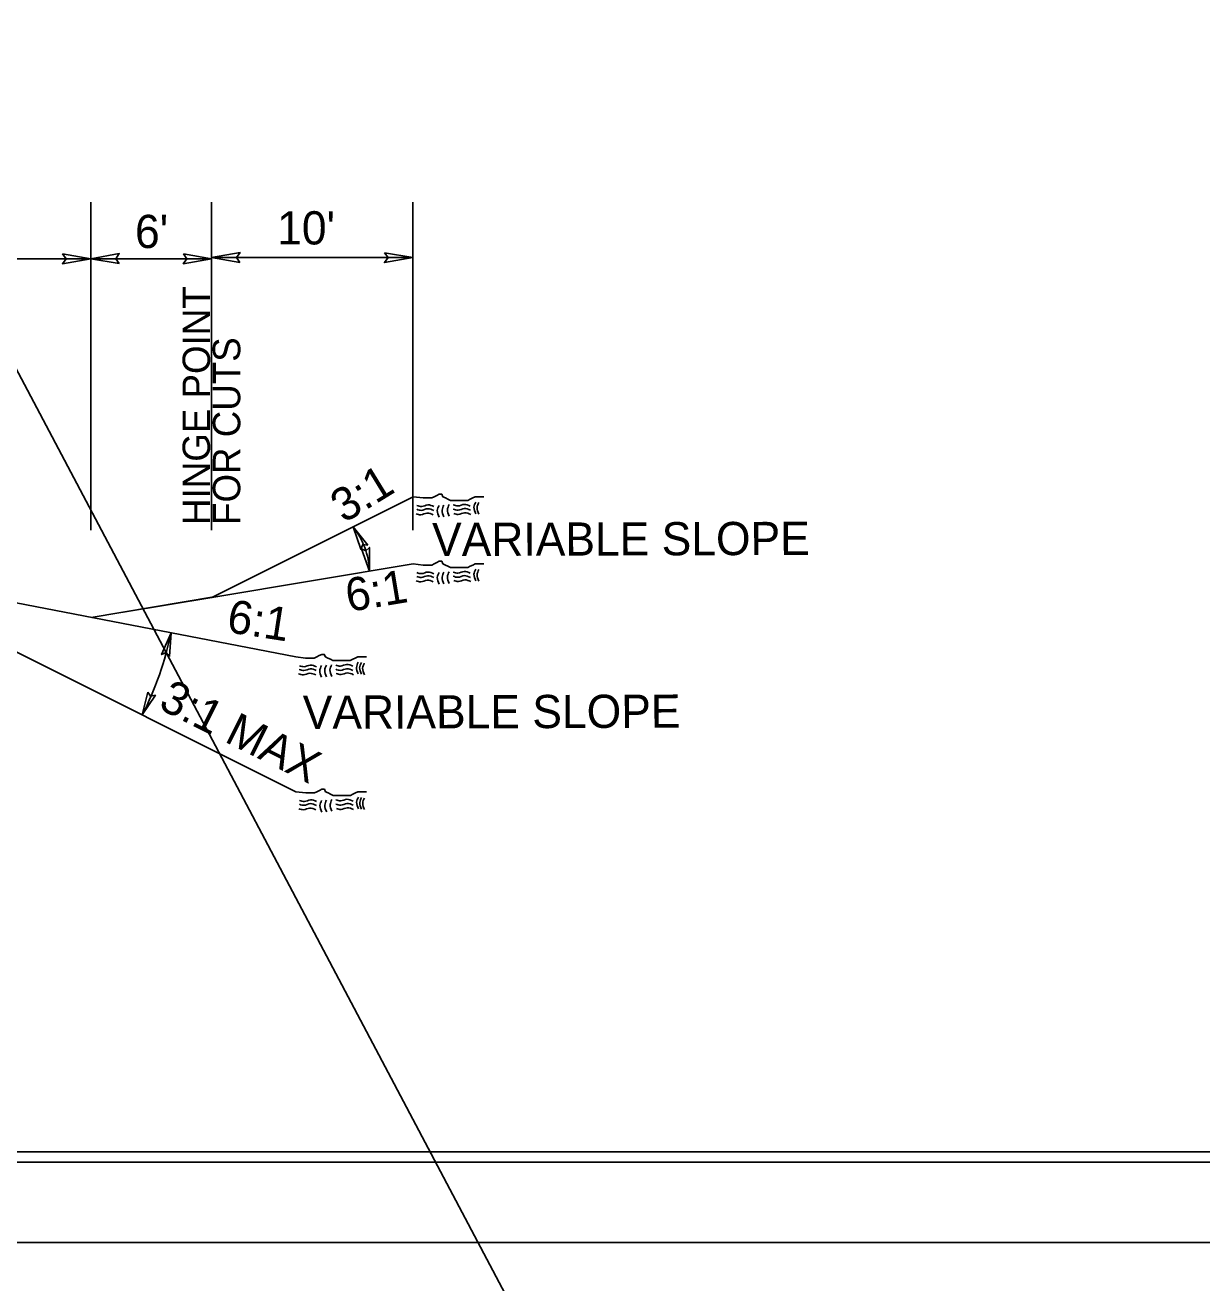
# Model space of a CAD drawing. Extents: x 2241081 to 2251104, y 658534 to 663427.
# Drawn here: x 2246466.3 to 2246758.6, y 660714.3 to 661026.7 of the extents above; entities that cross this region are included whole.
import ezdxf

# ---------------------------------------------------------------- set-up
doc = ezdxf.new("R2010")
doc.units = 0
for name, color, linetype in [('Old_Level_1', 7, 'Continuous'), ('Old_Level_2', 7, 'Continuous'), ('Prop Dimension', 7, 'Continuous'), ('Prop Dimension Text', 7, 'Continuous'), ('Prop PHM Text', 7, 'Continuous'), ('Sheet Cutting Line CELL', 7, 'Continuous'), ('Sheet Plan CELL', 7, 'Continuous'), ('Sheet Plot Border Inside CELL', 7, 'Continuous'), ('Sheet Plot Border Outside CELL', 7, 'Continuous'), ('Typical Hinge Slope Interstate CELL', 7, 'Continuous'), ('Typical Terminator CELL', 7, 'Continuous')]:
    doc.layers.add(name, color=color, linetype=linetype)

msp = doc.modelspace()

# ---------------------------------------------------------------- linework, layer by layer
at = {"layer": 'Old_Level_1'}
for p, q in [((2246562.71, 660909.54), (2246512.71, 660884.54)), ((2246512.71, 660884.54), (2246562.71, 660892.88)), ((2246424.69, 660890.71), (2246533.53, 660869.76)), ((2246512.71, 660884.54), (2246490.7, 660880.88))]:
    msp.add_line(p, q, dxfattribs=at)
for points in [[(2246562.71, 660909.54), (2246565.17, 660909.24), (2246565.79, 660909.24), (2246566.71, 660909.24), (2246567.33, 660909.24), (2246567.95, 660909.54), (2246568.56, 660909.85), (2246569.18, 660910.16), (2246569.8, 660910.16), (2246570.1, 660909.54), (2246570.72, 660909.24), (2246571.34, 660908.93), (2246571.95, 660908.62), (2246572.57, 660908.62), (2246573.19, 660908.62), (2246573.8, 660908.62), (2246574.42, 660908.62), (2246575.03, 660908.62), (2246575.65, 660908.62), (2246576.27, 660908.62), (2246576.88, 660908.93), (2246577.5, 660909.24), (2246578.11, 660909.54), (2246579.04, 660909.54), (2246579.66, 660909.54), (2246580.27, 660909.54)], [(2246562.71, 660892.88), (2246565.17, 660892.57), (2246565.79, 660892.57), (2246566.71, 660892.57), (2246567.33, 660892.57), (2246567.95, 660892.88), (2246568.56, 660893.19), (2246569.18, 660893.5), (2246569.8, 660893.5), (2246570.1, 660892.88), (2246570.72, 660892.57), (2246571.34, 660892.26), (2246571.95, 660891.96), (2246572.57, 660891.96), (2246573.19, 660891.96), (2246573.8, 660891.96), (2246574.42, 660891.96), (2246575.03, 660891.96), (2246575.65, 660891.96), (2246576.27, 660891.96), (2246576.88, 660892.26), (2246577.5, 660892.57), (2246578.11, 660892.88), (2246579.04, 660892.88), (2246579.66, 660892.88), (2246580.27, 660892.88)], [(2246533.53, 660869.76), (2246535.99, 660869.46), (2246536.61, 660869.46), (2246537.54, 660869.46), (2246538.15, 660869.46), (2246538.77, 660869.76), (2246539.38, 660870.07), (2246540, 660870.38), (2246540.62, 660870.38), (2246540.93, 660869.76), (2246541.54, 660869.46), (2246542.16, 660869.15), (2246542.77, 660868.84), (2246543.39, 660868.84), (2246544.01, 660868.84), (2246544.62, 660868.84), (2246545.24, 660868.84), (2246545.85, 660868.84), (2246546.47, 660868.84), (2246547.09, 660868.84), (2246547.7, 660869.15), (2246548.32, 660869.46), (2246548.93, 660869.76), (2246549.86, 660869.76), (2246550.48, 660869.76), (2246551.09, 660869.76)], [(2246533.57, 660836.27), (2246536.03, 660835.97), (2246536.65, 660835.97), (2246537.57, 660835.97), (2246538.19, 660835.97), (2246538.81, 660836.27), (2246539.42, 660836.58), (2246540.04, 660836.89), (2246540.65, 660836.89), (2246540.96, 660836.27), (2246541.58, 660835.97), (2246542.2, 660835.66), (2246542.81, 660835.35), (2246543.43, 660835.35), (2246544.04, 660835.35), (2246544.66, 660835.35), (2246545.28, 660835.35), (2246545.89, 660835.35), (2246546.51, 660835.35), (2246547.12, 660835.35), (2246547.74, 660835.66), (2246548.36, 660835.97), (2246548.97, 660836.27), (2246549.9, 660836.27), (2246550.51, 660836.27), (2246551.13, 660836.27)]]:
    msp.add_lwpolyline(points, dxfattribs=at)
for points in [[(2246578.24, 660908.18), (2246577.81, 660906.94), (2246578.27, 660905.29)], [(2246578.24, 660908.18), (2246577.81, 660906.94), (2246578.27, 660905.29)], [(2246579.02, 660908.1), (2246578.6, 660906.85), (2246579.06, 660905.21)], [(2246579.02, 660908.1), (2246578.6, 660906.85), (2246579.06, 660905.21)], [(2246567.69, 660905.03), (2246566.19, 660905.46), (2246564.59, 660905.06), (2246563.45, 660905.32)], [(2246567.69, 660905.03), (2246566.19, 660905.46), (2246564.59, 660905.06), (2246563.45, 660905.32)], [(2246567.84, 660906.12), (2246566.33, 660906.56), (2246564.75, 660906.15), (2246563.6, 660906.41)], [(2246567.84, 660906.12), (2246566.33, 660906.56), (2246564.75, 660906.15), (2246563.6, 660906.41)], [(2246567.88, 660907.07), (2246566.37, 660907.5), (2246564.79, 660907.09), (2246563.64, 660907.35)], [(2246567.88, 660907.07), (2246566.37, 660907.5), (2246564.79, 660907.09), (2246563.64, 660907.35)], [(2246569.13, 660907.36), (2246568.7, 660906.11), (2246569.16, 660904.47)], [(2246569.13, 660907.36), (2246568.7, 660906.11), (2246569.16, 660904.47)], [(2246570.34, 660907.46), (2246569.92, 660906.22), (2246570.37, 660904.57)], [(2246570.34, 660907.46), (2246569.92, 660906.22), (2246570.37, 660904.57)], [(2246571.65, 660907.57), (2246571.23, 660906.33), (2246571.68, 660904.68)], [(2246571.65, 660907.57), (2246571.23, 660906.33), (2246571.68, 660904.68)], [(2246576.91, 660907.21), (2246575.41, 660907.64), (2246573.81, 660907.24), (2246572.67, 660907.5)], [(2246576.91, 660907.21), (2246575.41, 660907.64), (2246573.81, 660907.24), (2246572.67, 660907.5)], [(2246576.92, 660906.17), (2246575.41, 660906.59), (2246573.83, 660906.18), (2246572.68, 660906.44)], [(2246576.92, 660906.17), (2246575.41, 660906.59), (2246573.83, 660906.18), (2246572.68, 660906.44)], [(2246577.03, 660905.11), (2246575.53, 660905.53), (2246573.93, 660905.14), (2246572.79, 660905.39)], [(2246577.03, 660905.11), (2246575.53, 660905.53), (2246573.93, 660905.14), (2246572.79, 660905.39)], [(2246567.84, 660889.46), (2246566.33, 660889.89), (2246564.75, 660889.48), (2246563.6, 660889.74)], [(2246567.84, 660889.46), (2246566.33, 660889.89), (2246564.75, 660889.48), (2246563.6, 660889.74)], [(2246567.88, 660890.4), (2246566.37, 660890.83), (2246564.79, 660890.43), (2246563.64, 660890.68)], [(2246567.88, 660890.4), (2246566.37, 660890.83), (2246564.79, 660890.43), (2246563.64, 660890.68)], [(2246569.13, 660890.69), (2246568.7, 660889.45), (2246569.16, 660887.8)], [(2246569.13, 660890.69), (2246568.7, 660889.45), (2246569.16, 660887.8)], [(2246570.34, 660890.8), (2246569.92, 660889.56), (2246570.37, 660887.91)], [(2246570.34, 660890.8), (2246569.92, 660889.56), (2246570.37, 660887.91)], [(2246571.65, 660890.9), (2246571.23, 660889.66), (2246571.68, 660888.01)], [(2246571.65, 660890.9), (2246571.23, 660889.66), (2246571.68, 660888.01)], [(2246576.91, 660890.55), (2246575.41, 660890.98), (2246573.81, 660890.57), (2246572.67, 660890.83)], [(2246576.91, 660890.55), (2246575.41, 660890.98), (2246573.81, 660890.57), (2246572.67, 660890.83)], [(2246576.92, 660889.5), (2246575.41, 660889.93), (2246573.83, 660889.52), (2246572.68, 660889.78)], [(2246576.92, 660889.5), (2246575.41, 660889.93), (2246573.83, 660889.52), (2246572.68, 660889.78)], [(2246578.24, 660891.51), (2246577.81, 660890.27), (2246578.27, 660888.63)], [(2246578.24, 660891.51), (2246577.81, 660890.27), (2246578.27, 660888.63)], [(2246579.02, 660891.43), (2246578.6, 660890.19), (2246579.06, 660888.54)], [(2246579.02, 660891.43), (2246578.6, 660890.19), (2246579.06, 660888.54)], [(2246567.69, 660888.37), (2246566.19, 660888.8), (2246564.59, 660888.39), (2246563.45, 660888.65)], [(2246567.69, 660888.37), (2246566.19, 660888.8), (2246564.59, 660888.39), (2246563.45, 660888.65)], [(2246577.03, 660888.44), (2246575.53, 660888.87), (2246573.93, 660888.47), (2246572.79, 660888.72)], [(2246577.03, 660888.44), (2246575.53, 660888.87), (2246573.93, 660888.47), (2246572.79, 660888.72)]]:
    msp.add_spline(points, degree=3, dxfattribs=at)
at = {"layer": 'Old_Level_2'}
msp.add_line((2247232.05, 659489.1), (2245149.47, 663427.07), dxfattribs=at)
for points in [[(2246538.7, 660867.29), (2246537.19, 660867.72), (2246535.61, 660867.31), (2246534.46, 660867.56)], [(2246538.7, 660867.29), (2246537.19, 660867.72), (2246535.61, 660867.31), (2246534.46, 660867.56)], [(2246539.95, 660867.57), (2246539.52, 660866.33), (2246539.98, 660864.69)], [(2246539.95, 660867.57), (2246539.52, 660866.33), (2246539.98, 660864.69)], [(2246541.16, 660867.68), (2246540.74, 660866.44), (2246541.19, 660864.79)], [(2246541.16, 660867.68), (2246540.74, 660866.44), (2246541.19, 660864.79)], [(2246542.47, 660867.78), (2246542.05, 660866.54), (2246542.5, 660864.9)], [(2246542.47, 660867.78), (2246542.05, 660866.54), (2246542.5, 660864.9)], [(2246547.73, 660867.43), (2246546.23, 660867.86), (2246544.63, 660867.46), (2246543.49, 660867.71)], [(2246547.73, 660867.43), (2246546.23, 660867.86), (2246544.63, 660867.46), (2246543.49, 660867.71)], [(2246549.06, 660868.4), (2246548.63, 660867.15), (2246549.09, 660865.51)], [(2246549.06, 660868.4), (2246548.63, 660867.15), (2246549.09, 660865.51)], [(2246549.84, 660868.32), (2246549.42, 660867.07), (2246549.88, 660865.42)], [(2246549.84, 660868.32), (2246549.42, 660867.07), (2246549.88, 660865.42)], [(2246550.57, 660868.17), (2246550.15, 660866.93), (2246550.6, 660865.29)], [(2246550.57, 660868.17), (2246550.15, 660866.93), (2246550.6, 660865.29)], [(2246538.51, 660865.25), (2246537.01, 660865.68), (2246535.41, 660865.28), (2246534.27, 660865.53)], [(2246538.66, 660866.34), (2246537.16, 660866.78), (2246535.57, 660866.37), (2246534.42, 660866.62)], [(2246538.66, 660866.34), (2246537.16, 660866.78), (2246535.57, 660866.37), (2246534.42, 660866.62)], [(2246547.74, 660866.38), (2246546.23, 660866.81), (2246544.65, 660866.4), (2246543.5, 660866.66)], [(2246547.74, 660866.38), (2246546.23, 660866.81), (2246544.65, 660866.4), (2246543.5, 660866.66)], [(2246547.86, 660865.33), (2246546.35, 660865.75), (2246544.76, 660865.35), (2246543.61, 660865.61)], [(2246547.86, 660865.33), (2246546.35, 660865.75), (2246544.76, 660865.35), (2246543.61, 660865.61)], [(2246538.7, 660832.85), (2246537.19, 660833.29), (2246535.61, 660832.88), (2246534.46, 660833.14)], [(2246538.7, 660832.85), (2246537.19, 660833.29), (2246535.61, 660832.88), (2246534.46, 660833.14)], [(2246538.74, 660833.8), (2246537.23, 660834.23), (2246535.65, 660833.82), (2246534.5, 660834.08)], [(2246538.74, 660833.8), (2246537.23, 660834.23), (2246535.65, 660833.82), (2246534.5, 660834.08)], [(2246539.98, 660834.08), (2246539.56, 660832.84), (2246540.02, 660831.2)], [(2246539.98, 660834.08), (2246539.56, 660832.84), (2246540.02, 660831.2)], [(2246541.2, 660834.19), (2246540.77, 660832.95), (2246541.23, 660831.3)], [(2246541.2, 660834.19), (2246540.77, 660832.95), (2246541.23, 660831.3)], [(2246542.51, 660834.29), (2246542.09, 660833.05), (2246542.54, 660831.41)], [(2246542.51, 660834.29), (2246542.09, 660833.05), (2246542.54, 660831.41)], [(2246547.77, 660833.94), (2246546.27, 660834.37), (2246544.67, 660833.97), (2246543.53, 660834.23)], [(2246547.77, 660833.94), (2246546.27, 660834.37), (2246544.67, 660833.97), (2246543.53, 660834.23)], [(2246547.78, 660832.89), (2246546.27, 660833.32), (2246544.69, 660832.91), (2246543.54, 660833.17)], [(2246547.78, 660832.89), (2246546.27, 660833.32), (2246544.69, 660832.91), (2246543.54, 660833.17)], [(2246549.1, 660834.91), (2246548.67, 660833.66), (2246549.13, 660832.02)], [(2246549.1, 660834.91), (2246548.67, 660833.66), (2246549.13, 660832.02)], [(2246549.88, 660834.83), (2246549.46, 660833.58), (2246549.91, 660831.93)], [(2246549.88, 660834.83), (2246549.46, 660833.58), (2246549.91, 660831.93)], [(2246550.61, 660834.68), (2246550.18, 660833.44), (2246550.64, 660831.8)], [(2246550.61, 660834.68), (2246550.18, 660833.44), (2246550.64, 660831.8)], [(2246538.55, 660831.76), (2246537.04, 660832.19), (2246535.45, 660831.79), (2246534.31, 660832.04)], [(2246547.89, 660831.84), (2246546.39, 660832.26), (2246544.79, 660831.86), (2246543.65, 660832.12)], [(2246547.89, 660831.84), (2246546.39, 660832.26), (2246544.79, 660831.86), (2246543.65, 660832.12)]]:
    msp.add_spline(points, degree=3, dxfattribs=at)
at = {"layer": 'Prop Dimension'}
for centre, radius, start, end in [((2246532.77, 660890.22), 19.12, 2.5693, 38.3323), ((2246423.2, 660892.13), 81.05, 333.0098, 348.3211)]:
    msp.add_arc(centre, radius, start, end, dxfattribs=at)
at = {"layer": 'Prop Dimension Text'}
for p, q in [((2246482.66, 660901.26), (2246482.66, 660982.73)), ((2246512.66, 660901.26), (2246512.66, 660982.73)), ((2246562.66, 660901.26), (2246562.66, 660982.73)), ((2246424.65, 660968.66), (2246482.66, 660968.66)), ((2246482.66, 660968.66), (2246512.66, 660968.66)), ((2246512.66, 660969.05), (2246512.66, 660969.05)), ((2246512.66, 660968.92), (2246562.66, 660968.92)), ((2246562.66, 660969.05), (2246562.66, 660969.05))]:
    msp.add_line(p, q, dxfattribs=at)
at = {"layer": 'Sheet Cutting Line CELL'}
for p, q in [((2245397.32, 660724.27), (2247080.82, 660724.27)), ((2247080.82, 660724.27), (2245397.32, 660724.27))]:
    msp.add_line(p, q, dxfattribs=at)
at = {"layer": 'Sheet Plan CELL'}
for points in [[(2245563.81, 660746.78), (2245563.79, 661796.76), (2246863.78, 661796.79), (2246863.79, 661646.73), (2247063.83, 661646.72), (2247063.82, 660746.78)], [(2247063.85, 661796.78), (2245563.81, 661796.78), (2245563.81, 660746.78), (2247063.82, 660746.78)]]:
    msp.add_lwpolyline(points, close=True, dxfattribs=at)
at = {"layer": 'Sheet Plot Border Inside CELL'}
msp.add_lwpolyline([(2245410.32, 660744.27), (2247076.31, 660744.28), (2247076.33, 661799.27), (2245410.33, 661799.27)], close=True, dxfattribs=at)
at = {"layer": 'Sheet Plot Border Outside CELL'}
for points in [[(2245397.32, 660724.27), (2247080.82, 660724.27), (2247080.83, 661819.27), (2245397.33, 661819.27)], [(2245397.32, 659629.27), (2247080.82, 659629.27), (2247080.82, 660724.27), (2245397.32, 660724.27)]]:
    msp.add_lwpolyline(points, close=True, dxfattribs=at)
at = {"layer": 'Typical Hinge Slope Interstate CELL'}
for p, q in [((2246424.69, 660890.71), (2246533.57, 660836.27)), ((2246513.2, 660884.63), (2246482.71, 660879.54))]:
    msp.add_line(p, q, dxfattribs=at)
at = {"layer": 'Typical Terminator CELL'}
for points in [[(2246519.69, 660967.71), (2246512.66, 660968.92), (2246519.73, 660970.17), (2246518.83, 660968.92)], [(2246475.63, 660969.87), (2246482.66, 660968.66), (2246475.59, 660967.41), (2246476.49, 660968.66)], [(2246489.69, 660967.45), (2246482.66, 660968.66), (2246489.73, 660969.91), (2246488.83, 660968.66)], [(2246505.63, 660969.87), (2246512.66, 660968.66), (2246505.59, 660967.41), (2246506.49, 660968.66)], [(2246555.63, 660970.13), (2246562.66, 660968.92), (2246555.59, 660967.67), (2246556.49, 660968.92)], [(2246551.43, 660897.51), (2246547.77, 660902.07), (2246549.68, 660896.5), (2246550.22, 660897.64)], [(2246549.87, 660896.57), (2246551.87, 660891.07), (2246551.85, 660896.96), (2246550.97, 660896.06)], [(2246502.19, 660869.88), (2246502.58, 660875.72), (2246500.22, 660870.32), (2246501.39, 660870.8)], [(2246496.84, 660861.02), (2246495.43, 660855.34), (2246498.7, 660860.24), (2246497.47, 660859.98)]]:
    msp.add_lwpolyline(points, close=True, dxfattribs=at)

# ---------------------------------------------------------------- texts
at = {"layer": 'Prop Dimension Text'}
for s, rotation, p in [("6'", 359.9999, (2246493.62, 660971.3)), ("10'", 359.9999, (2246528.93, 660972.19)), ('6:1', 351.1342, (2246516.16, 660875.94))]:
    msp.add_text(s, height=8.25, rotation=rotation, dxfattribs=at).set_placement(p)
at = {"layer": 'Prop PHM Text'}
for s, height, p in [('HINGE POINT', 6.8193, (2246512.26, 660902.52)), ('FOR CUTS', 6.819, (2246519.77, 660902.52))]:
    msp.add_text(s, height=height, rotation=89.9999, dxfattribs=at).set_placement(p)
at = {"layer": 'Typical Hinge Slope Interstate CELL'}
for s, rotation, p in [('3:1', 31.5585, (2246545.54, 660902.83)), ('VARIABLE SLOPE', 0.1842, (2246567.42, 660894.78)), ('6:1', 9.4623, (2246546.65, 660880.89)), ('3:1 MAX', 333.4356, (2246499.13, 660857.05)), ('VARIABLE SLOPE', 0.1842, (2246535.3, 660851.86))]:
    msp.add_text(s, height=8.25, rotation=rotation, dxfattribs=at).set_placement(p)

doc.saveas('drawing.dxf')
